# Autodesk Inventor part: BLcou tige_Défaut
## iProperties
Shininess: 64.0
Length Units: 11269
Angle Units: 11279
Time Units: 11290
Mass Units: 11283
Length Display Precision: 3
Angle Display Precision: 2
Compacted: True
Part Number: BLcou tige_Défaut
Document SubType Name: Modeling
Created: 2006-11
Material: Par défaut
Designer: profs_sti
Density: 0.0
Volumn: 0.0
Area: 0.0
PropertySet Name: Model Information
Control State: 0
Master: False
Checked Out: False
Author: profs_sti
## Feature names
1. Base1
